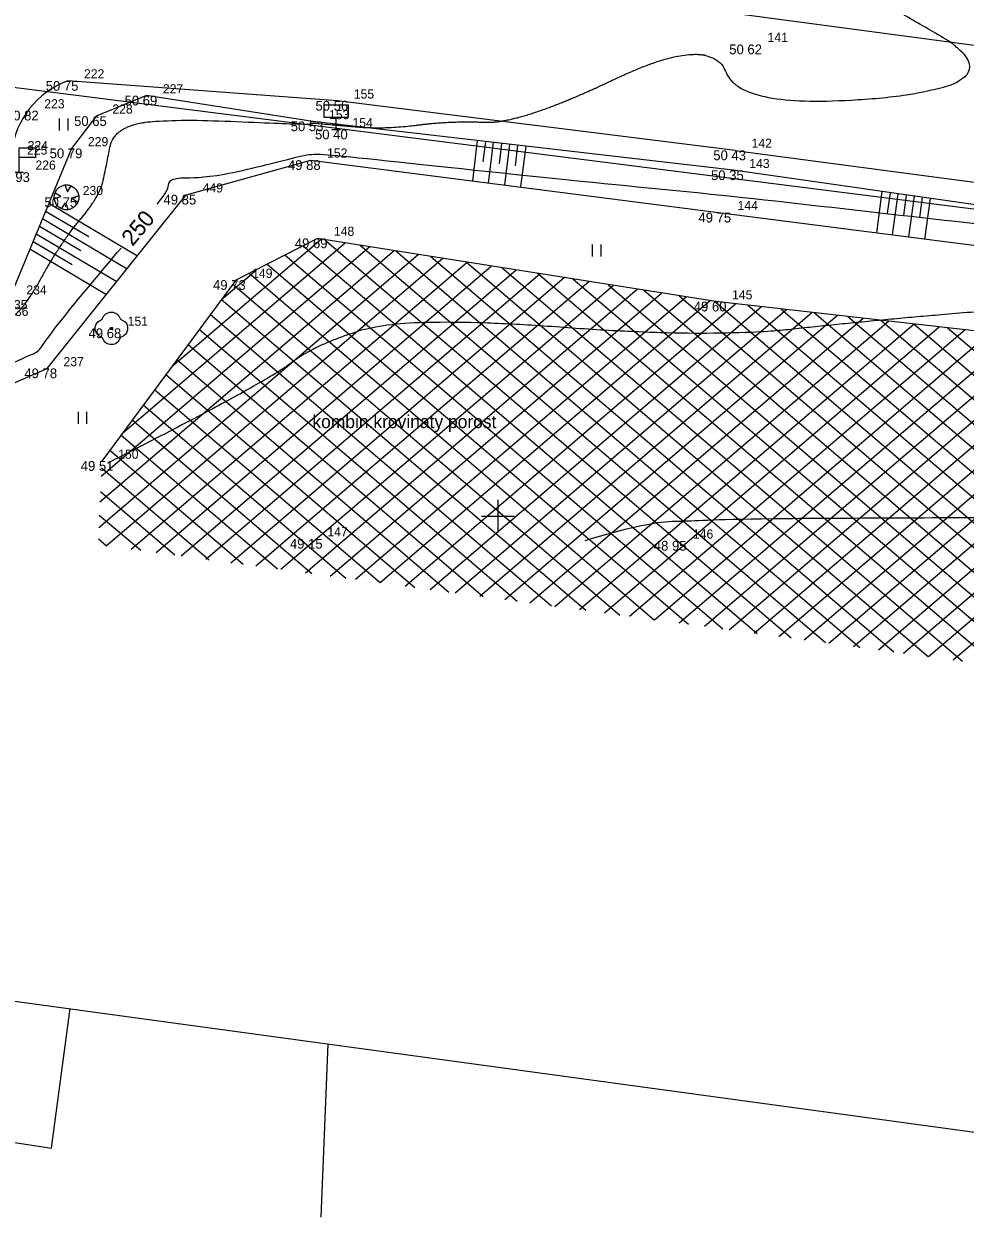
# Model space of a CAD drawing. Extents: x -704057 to -703795, y -1008732 to -1008584.
# Drawn here: x -703939.55 to -703910.66, y -1008696.51 to -1008659.9 of the extents above; entities that cross this region are included whole.
import ezdxf

# ---------------------------------------------------------------- set-up
doc = ezdxf.new("R2010")
doc.units = 0
for name, color, linetype in [('Z_body', 7, 'Continuous'), ('Z_body_cisla', 7, 'Continuous'), ('Z_body_vysky', 7, 'Continuous'), ('Z_dopravni_znaceni', 7, 'Continuous'), ('Z_hekt_sit', 7, 'Continuous'), ('Z_katastr_hranice', 7, 'Continuous'), ('Z_katastr_hranice_KU', 7, 'Continuous'), ('Z_katastr_vnitrni_kresba', 7, 'Continuous'), ('Z_komunikace_zpevn_pl', 7, 'Continuous'), ('Z_popis', 7, 'Continuous'), ('Z_teren_hrany_paty', 7, 'Continuous'), ('Z_vrstevnice_popis', 7, 'Continuous'), ('Z_vrstevnice_vedlejsi', 7, 'Continuous'), ('Z_zelen_jednotliva', 7, 'Continuous'), ('Z_zelen_souvisla', 7, 'Continuous')]:
    doc.layers.add(name, color=color, linetype=linetype)

# ---------------------------------------------------------------- blocks, each defined once
blk = doc.blocks.new('POINT_DISPLAY')
blk.add_line((0, 0), (0, 0))
blk = doc.blocks.new('Z24')
for p, q in [((-0.28, 0.28), (-0.23, 0.38)), ((-0.23, 0.38), (-0.17, 0.45)), ((-0.17, 0.45), (-0.05, 0.5)), ((-0.05, 0.5), (0.05, 0.5)), ((0.05, 0.5), (0.17, 0.45)), ((0.17, 0.45), (0.23, 0.38)), ((0.23, 0.38), (0.28, 0.28)), ((-0.5, 0.05), (-0.47, 0.13)), ((-0.5, -0.05), (-0.5, 0.05)), ((-0.47, 0.13), (-0.42, 0.2)), ((-0.42, 0.2), (-0.28, 0.28)), ((-0.03, -0.03), (-0.03, 0.03)), ((-0.03, 0.03), (0.03, 0.03)), ((0.03, 0.03), (0.03, -0.03)), ((0.28, 0.28), (0.42, 0.2)), ((0.42, 0.2), (0.47, 0.13)), ((0.47, 0.13), (0.5, 0.05)), ((0.5, 0.05), (0.5, -0.05)), ((-0.45, -0.17), (-0.5, -0.05)), ((-0.38, -0.23), (-0.45, -0.17)), ((-0.28, -0.28), (-0.38, -0.23)), ((-0.2, -0.42), (-0.28, -0.28)), ((0.03, -0.03), (-0.03, -0.03)), ((0.28, -0.28), (0.2, -0.42)), ((0.38, -0.23), (0.28, -0.28)), ((0.45, -0.17), (0.38, -0.23)), ((0.5, -0.05), (0.45, -0.17)), ((-0.13, -0.47), (-0.2, -0.42)), ((-0.05, -0.5), (-0.13, -0.47)), ((0.05, -0.5), (-0.05, -0.5)), ((0.13, -0.47), (0.05, -0.5)), ((0.2, -0.42), (0.13, -0.47))]:
    blk.add_line(p, q)
blk = doc.blocks.new('Z23')
for p, q in [((-0.13, 0.35), (-0.05, 0.38)), ((-0.05, 0.38), (0.05, 0.38)), ((-0.05, 0.38), (0.03, 0.17)), ((0.05, 0.38), (0.15, 0.35)), ((-0.38, 0.05), (-0.35, 0.13)), ((-0.38, -0.05), (-0.38, 0.05)), ((-0.38, -0.05), (-0.17, 0.03)), ((-0.35, 0.13), (-0.3, 0.23)), ((-0.17, 0.03), (-0.35, 0.13)), ((-0.3, 0.23), (-0.23, 0.3)), ((-0.23, 0.3), (-0.13, 0.35)), ((0.03, 0.17), (0.15, 0.35)), ((0.15, 0.35), (0.23, 0.3)), ((0.38, 0.05), (0.17, -0.03)), ((0.23, 0.3), (0.3, 0.23)), ((0.3, 0.23), (0.35, 0.15)), ((0.35, 0.15), (0.38, 0.05)), ((0.38, 0.05), (0.38, -0.05)), ((-0.35, -0.13), (-0.38, -0.05)), ((-0.3, -0.23), (-0.35, -0.13)), ((-0.23, -0.3), (-0.3, -0.23)), ((-0.15, -0.35), (-0.23, -0.3)), ((-0.15, -0.35), (-0.03, -0.17)), ((-0.05, -0.38), (-0.15, -0.35)), ((-0.03, -0.17), (0.05, -0.38)), ((0.15, -0.35), (0.05, -0.38)), ((0.23, -0.3), (0.15, -0.35)), ((0.17, -0.03), (0.35, -0.15)), ((0.3, -0.23), (0.23, -0.3)), ((0.35, -0.15), (0.3, -0.23)), ((0.38, -0.05), (0.35, -0.15)), ((0.05, -0.38), (-0.05, -0.38))]:
    blk.add_line(p, q)
blk = doc.blocks.new('Z524')
for p, q in [((0, 0), (0, 0.75)), ((0, 0.75), (0.5, 0.75)), ((0.5, 0.75), (0.5, 0.45)), ((0.5, 0.45), (0, 0.45)), ((-0.13, 0), (0.13, 0))]:
    blk.add_line(p, q)
blk = doc.blocks.new('Z526')
for p, q in [((0.38, 0.75), (-0.38, 0.75)), ((-0.38, 0.75), (-0.38, 0.38)), ((0.38, 0.38), (0.38, 0.75)), ((-0.38, 0.38), (0.38, 0.38)), ((0, 0), (0, 0.38)), ((-0.13, 0), (0.13, 0))]:
    blk.add_line(p, q)
blk = doc.blocks.new('Z306')
for p, q in [((-0.13, 0.17), (-0.13, -0.2)), ((0.13, 0.17), (0.13, -0.2))]:
    blk.add_line(p, q)

msp = doc.modelspace()

# ---------------------------------------------------------------- linework, layer by layer
at = {"layer": 'Z_hekt_sit'}
for p, q in [((-703925, -1008674.5), (-703925, -1008675.5)), ((-703925.5, -1008675), (-703924.5, -1008675))]:
    msp.add_line(p, q, dxfattribs=at)
at = {"layer": 'Z_katastr_hranice'}
for p, q in [((-703947.65, -1008660.85), (-703907.73, -1008665.91)), ((-703972.28, -1008685.45), (-703894.62, -1008696.05)), ((-703930.42, -1008696.51), (-703930.21, -1008691.19))]:
    msp.add_line(p, q, dxfattribs=at)
at = {"layer": 'Z_katastr_hranice_KU'}
msp.add_line((-703947.15, -1008655.63), (-703906.73, -1008661.04), dxfattribs=at)
at = {"layer": 'Z_katastr_vnitrni_kresba'}
for p, q in [((-703938.7, -1008694.39), (-703938.12, -1008690.11)), ((-703950.63, -1008692.56), (-703938.7, -1008694.39))]:
    msp.add_line(p, q, dxfattribs=at)
at = {"layer": 'Z_komunikace_zpevn_pl'}
for p, q in [((-703929.92, -1008662.26), (-703938.2, -1008661.65)), ((-703917.71, -1008663.78), (-703929.92, -1008662.26)), ((-703917.71, -1008663.78), (-703906.76, -1008665.24))]:
    msp.add_line(p, q, dxfattribs=at)
msp.add_arc((-703937.28, -1008664.15), 2.666, 110.1364, 173.2493, dxfattribs=at)
at = {"layer": 'Z_teren_hrany_paty'}
for p, q in [((-703935.78, -1008662.1), (-703937.33, -1008662.73)), ((-703930.68, -1008662.89), (-703935.78, -1008662.1)), ((-703937.33, -1008662.73), (-703938.08, -1008663.72)), ((-703917.78, -1008664.39), (-703930.68, -1008662.89)), ((-703925.63, -1008663.48), (-703925.78, -1008664.71)), ((-703925.38, -1008663.51), (-703925.46, -1008664.13)), ((-703925.14, -1008663.53), (-703925.29, -1008664.78)), ((-703924.89, -1008663.56), (-703924.96, -1008664.19)), ((-703924.64, -1008663.59), (-703924.79, -1008664.84)), ((-703938.08, -1008663.72), (-703939.97, -1008668.27)), ((-703924.39, -1008663.62), (-703924.47, -1008664.25)), ((-703924.14, -1008663.65), (-703924.3, -1008664.9)), ((-703934.56, -1008665.14), (-703930.74, -1008664.08)), ((-703930.74, -1008664.08), (-703918.14, -1008665.69)), ((-703907.01, -1008665.93), (-703917.78, -1008664.39)), ((-703913.21, -1008665.04), (-703913.38, -1008666.31)), ((-703938.83, -1008670.47), (-703934.56, -1008665.14)), ((-703938.78, -1008665.4), (-703936.06, -1008667.01)), ((-703912.96, -1008665.08), (-703913.05, -1008665.71)), ((-703912.72, -1008665.11), (-703912.89, -1008666.37)), ((-703912.47, -1008665.15), (-703912.55, -1008665.78)), ((-703912.22, -1008665.18), (-703912.39, -1008666.43)), ((-703911.97, -1008665.22), (-703912.06, -1008665.84)), ((-703911.73, -1008665.26), (-703911.9, -1008666.5)), ((-703938.88, -1008665.64), (-703937.55, -1008666.42)), ((-703918.14, -1008665.69), (-703907.01, -1008667.13)), ((-703939.07, -1008666.1), (-703937.8, -1008666.85)), ((-703938.97, -1008665.87), (-703936.38, -1008667.41)), ((-703939.17, -1008666.34), (-703936.69, -1008667.8)), ((-703939.36, -1008666.8), (-703937.01, -1008668.2)), ((-703939.26, -1008666.57), (-703938.06, -1008667.28)), ((-703940.68, -1008671.28), (-703938.83, -1008670.47))]:
    msp.add_line(p, q, dxfattribs=at)
at = {"layer": 'Z_vrstevnice_popis'}
for points in [[(-703935.451, -1008665.426), (-703935.149, -1008665.04), (-703935.119, -1008664.898), (-703935.079, -1008664.688), (-703934.778, -1008664.597), (-703933.704, -1008664.644), (-703930.729, -1008663.86), (-703930.56, -1008663.863), (-703922.686, -1008664.709), (-703917.99, -1008665.148), (-703912.22, -1008665.818), (-703907.01, -1008666.385), (-703897.89, -1008667.322), (-703895.624, -1008667.536), (-703894.683, -1008667.62), (-703889.646, -1008668.109), (-703886.88, -1008668.055), (-703885.948, -1008667.981), (-703882.942, -1008667.846), (-703876.005, -1008667.766), (-703871.926, -1008667.612), (-703869.247, -1008667.54), (-703868.688, -1008667.52)], [(-703943.199, -1008670.586), (-703942.532, -1008670.689), (-703942.405, -1008670.67), (-703940.763, -1008670.903), (-703940.641, -1008670.668), (-703939.322, -1008670.024), (-703939.083, -1008669.981), (-703938.742, -1008669.363), (-703937.122, -1008667.441), (-703936.564, -1008666.776)], [(-703922.315, -1008675.745), (-703920.255, -1008675.133), (-703919.418, -1008675.195), (-703918.102, -1008675.05), (-703907.476, -1008675.061), (-703903.573, -1008674.82), (-703895.854, -1008673.376), (-703883.381, -1008672.872), (-703883.154, -1008672.873), (-703883.026, -1008672.86), (-703882.713, -1008672.828), (-703878.528, -1008672.795), (-703877.019, -1008672.782)]]:
    msp.add_open_spline(points, degree=3, dxfattribs=at)
at = {"layer": 'Z_vrstevnice_vedlejsi'}
for points in [[(-703944.218, -1008669.537), (-703942.215, -1008669.847), (-703941.835, -1008669.79), (-703940.983, -1008669.911), (-703940.538, -1008669.059), (-703940.441, -1008669.011), (-703939.659, -1008668.87), (-703938.392, -1008666.573), (-703937.218, -1008665.198), (-703936.994, -1008664.158), (-703936.811, -1008663.182), (-703935.504, -1008662.788), (-703930.851, -1008662.989), (-703930.683, -1008662.945), (-703930.514, -1008662.948), (-703928.53, -1008663.14), (-703926.451, -1008662.869), (-703924.285, -1008662.962), (-703918.453, -1008660.188), (-703917.529, -1008662.583), (-703908.804, -1008661.73), (-703914.417, -1008658.58), (-703914.255, -1008657.775), (-703916.458, -1008657.408), (-703916.075, -1008656.975), (-703916.505, -1008656.883), (-703916.435, -1008655.703), (-703915.746, -1008656.007), (-703915.438, -1008656.225), (-703913.541, -1008656.36), (-703913.202, -1008656.502), (-703907.93, -1008657.256), (-703905.824, -1008657.417), (-703900.033, -1008658.024), (-703894.345, -1008658.848), (-703890.179, -1008659.57), (-703887.702, -1008659.871), (-703882.266, -1008660.175), (-703878.347, -1008660.959), (-703873.149, -1008661.531), (-703869.803, -1008661.293), (-703867.148, -1008661.514), (-703856.66, -1008662.48), (-703848.555, -1008661.935), (-703843.582, -1008661.747), (-703840.018, -1008661.713), (-703835.656, -1008661.182), (-703832.168, -1008661.259), (-703831.497, -1008661.293), (-703819.488, -1008662.346), (-703817.521, -1008662.543), (-703807.841, -1008663.114), (-703805.78, -1008663.132)], [(-703806.645, -1008669.413), (-703810.064, -1008669.091), (-703818.896, -1008668.231), (-703821.949, -1008667.886), (-703832.348, -1008666.911), (-703832.429, -1008666.905), (-703837.82, -1008666.255), (-703832.713, -1008666.908), (-703832.355, -1008666.952), (-703825.705, -1008667.99), (-703819.056, -1008669.026), (-703815.993, -1008669.415), (-703810.462, -1008670.24), (-703806.87, -1008671.09), (-703808.766, -1008673.591), (-703809.75, -1008673.886), (-703817.454, -1008673.52), (-703819.628, -1008673.248), (-703826.836, -1008673.24), (-703833.27, -1008673.353), (-703835.286, -1008673.278), (-703844.44, -1008672.81), (-703850.152, -1008672.821), (-703855.806, -1008672.275), (-703857.13, -1008672.165), (-703860.162, -1008671.947), (-703871.237, -1008671.005), (-703876.973, -1008670.473), (-703883.276, -1008669.953), (-703888.652, -1008669.207), (-703892.007, -1008668.787), (-703895.701, -1008668.459), (-703900.931, -1008667.965), (-703907.22, -1008668.487), (-703913.351, -1008668.979), (-703918.495, -1008669.549), (-703927.701, -1008668.863), (-703930.6, -1008669.724), (-703932.124, -1008670.909), (-703936.972, -1008673.376)]]:
    msp.add_open_spline(points, degree=2, dxfattribs=at)
at = {"layer": 'Z_zelen_souvisla'}
for p, q in [((-703935, -1008670.41), (-703930.42, -1008666.5)), ((-703930.53, -1008666.48), (-703933.04, -1008667.76)), ((-703918.31, -1008668.42), (-703930.53, -1008666.48)), ((-703930.31, -1008666.52), (-703915.99, -1008678.74)), ((-703937.21, -1008674.56), (-703928.18, -1008666.85)), ((-703937.17, -1008673.77), (-703928.93, -1008666.73)), ((-703936.52, -1008672.46), (-703929.68, -1008666.62)), ((-703930.97, -1008666.71), (-703917.04, -1008678.6)), ((-703929.22, -1008666.69), (-703914.94, -1008678.88)), ((-703928.13, -1008666.86), (-703913.89, -1008679.03)), ((-703937.25, -1008675.35), (-703927.44, -1008666.97)), ((-703937.02, -1008675.91), (-703926.69, -1008667.09)), ((-703936.25, -1008676.01), (-703925.94, -1008667.21)), ((-703931.53, -1008666.99), (-703918.09, -1008678.46)), ((-703927.05, -1008667.03), (-703912.84, -1008679.17)), ((-703925.96, -1008667.21), (-703911.79, -1008679.31)), ((-703935.49, -1008676.12), (-703925.2, -1008667.33)), ((-703934.72, -1008676.22), (-703924.45, -1008667.45)), ((-703933.96, -1008676.32), (-703923.7, -1008667.56)), ((-703933.48, -1008668.35), (-703932.41, -1008667.44)), ((-703932.63, -1008667.55), (-703920.2, -1008678.18)), ((-703932.08, -1008667.27), (-703919.15, -1008678.32)), ((-703924.87, -1008667.38), (-703910.74, -1008679.45)), ((-703923.78, -1008667.55), (-703909.68, -1008679.59)), ((-703933.04, -1008667.76), (-703937.15, -1008673.31)), ((-703933.19, -1008676.43), (-703922.96, -1008667.68)), ((-703933.13, -1008667.88), (-703921.25, -1008678.04)), ((-703932.43, -1008676.53), (-703922.21, -1008667.8)), ((-703931.66, -1008676.63), (-703921.46, -1008667.92)), ((-703922.7, -1008667.72), (-703908.63, -1008679.73)), ((-703921.61, -1008667.9), (-703907.58, -1008679.88)), ((-703933.48, -1008668.35), (-703922.3, -1008677.89)), ((-703930.9, -1008676.74), (-703920.72, -1008668.04)), ((-703930.14, -1008676.84), (-703919.97, -1008668.16)), ((-703929.37, -1008676.94), (-703919.22, -1008668.27)), ((-703920.52, -1008668.07), (-703906.53, -1008680.02)), ((-703919.43, -1008668.24), (-703905.48, -1008680.16)), ((-703928.61, -1008677.04), (-703918.48, -1008668.39)), ((-703927.84, -1008677.15), (-703917.7, -1008668.49)), ((-703927.08, -1008677.25), (-703916.92, -1008668.58)), ((-703926.31, -1008677.35), (-703916.14, -1008668.66)), ((-703918.35, -1008668.41), (-703904.43, -1008680.3)), ((-703907.4, -1008669.65), (-703918.31, -1008668.42)), ((-703917.32, -1008668.53), (-703903.38, -1008680.44)), ((-703916.3, -1008668.65), (-703902.33, -1008680.58)), ((-703933.82, -1008668.81), (-703923.35, -1008677.75)), ((-703925.55, -1008677.46), (-703915.36, -1008668.75)), ((-703924.78, -1008677.56), (-703914.57, -1008668.84)), ((-703924.02, -1008677.66), (-703913.79, -1008668.93)), ((-703923.25, -1008677.77), (-703913.01, -1008669.02)), ((-703915.28, -1008668.76), (-703901.28, -1008680.73)), ((-703914.26, -1008668.88), (-703900.22, -1008680.87)), ((-703913.24, -1008668.99), (-703899.17, -1008681.01)), ((-703934.16, -1008669.27), (-703924.4, -1008677.61)), ((-703922.49, -1008677.87), (-703912.23, -1008669.11)), ((-703921.72, -1008677.97), (-703911.45, -1008669.19)), ((-703920.96, -1008678.07), (-703910.66, -1008669.28)), ((-703920.19, -1008678.18), (-703909.88, -1008669.37)), ((-703919.43, -1008678.28), (-703909.1, -1008669.46)), ((-703912.22, -1008669.11), (-703898.12, -1008681.15)), ((-703911.2, -1008669.22), (-703897.07, -1008681.29)), ((-703934.5, -1008669.74), (-703925.45, -1008677.47)), ((-703918.66, -1008678.38), (-703908.32, -1008669.55)), ((-703917.9, -1008678.49), (-703907.54, -1008669.63)), ((-703917.13, -1008678.59), (-703906.75, -1008669.72)), ((-703916.37, -1008678.69), (-703905.96, -1008669.81)), ((-703915.6, -1008678.8), (-703905.18, -1008669.89)), ((-703914.84, -1008678.9), (-703904.39, -1008669.98)), ((-703914.08, -1008679), (-703903.61, -1008670.06)), ((-703913.31, -1008679.1), (-703902.82, -1008670.15)), ((-703934.85, -1008670.2), (-703926.5, -1008677.33)), ((-703912.55, -1008679.21), (-703902.04, -1008670.23)), ((-703911.78, -1008679.31), (-703901.25, -1008670.32)), ((-703911.02, -1008679.41), (-703900.47, -1008670.4)), ((-703935.19, -1008670.66), (-703927.55, -1008677.19)), ((-703935.53, -1008671.13), (-703928.61, -1008677.04)), ((-703935.88, -1008671.59), (-703929.66, -1008676.9)), ((-703936.22, -1008672.05), (-703930.71, -1008676.76)), ((-703936.56, -1008672.52), (-703931.76, -1008676.62)), ((-703936.91, -1008672.98), (-703932.81, -1008676.48)), ((-703937.16, -1008673.52), (-703933.86, -1008676.34)), ((-703937.19, -1008674.25), (-703934.91, -1008676.19)), ((-703937.23, -1008674.97), (-703935.96, -1008676.05)), ((-703937.26, -1008675.7), (-703937.01, -1008675.91))]:
    msp.add_line(p, q, dxfattribs=at)

# ---------------------------------------------------------------- block references
at = {"layer": 'Z_body'}
for p in [(-703917.22, -1008660.53), (-703938.2, -1008661.65), (-703935.78, -1008662.1), (-703929.92, -1008662.26), (-703939.42, -1008662.56), (-703937.33, -1008662.73), (-703930.68, -1008662.89), (-703929.96, -1008663.14), (-703938.08, -1008663.72), (-703917.71, -1008663.78), (-703930.74, -1008664.08), (-703917.78, -1008664.39), (-703938.24, -1008665.22), (-703934.56, -1008665.14), (-703918.14, -1008665.69), (-703930.53, -1008666.48), (-703933.04, -1008667.76), (-703918.31, -1008668.42), (-703936.86, -1008669.24), (-703938.83, -1008670.47), (-703937.15, -1008673.31), (-703930.73, -1008675.7), (-703919.51, -1008675.76)]:
    msp.add_blockref('POINT_DISPLAY', p, dxfattribs=at)
at = {"layer": 'Z_dopravni_znaceni'}
for name, p in [('Z526', (-703929.96, -1008663.14)), ('Z524', (-703939.69, -1008664.45))]:
    msp.add_blockref(name, p, dxfattribs=at)
at = {"layer": 'Z_popis'}
for p in [(-703938.33, -1008662.97), (-703921.97, -1008666.84), (-703937.75, -1008671.97)]:
    msp.add_blockref('Z306', p, dxfattribs=at)
at = {"layer": 'Z_zelen_jednotliva'}
for name, p in [('Z23', (-703938.24, -1008665.22)), ('Z24', (-703936.86, -1008669.24))]:
    msp.add_blockref(name, p, dxfattribs=at)

# ---------------------------------------------------------------- texts
at = {"layer": 'Z_body_cisla'}
for s, p in [('141', (-703916.72, -1008660.45)), ('222', (-703937.7, -1008661.57)), ('227', (-703935.28, -1008662.03)), ('155', (-703929.42, -1008662.19)), ('223', (-703938.92, -1008662.49)), ('228', (-703936.83, -1008662.65)), ('153', (-703930.18, -1008662.82)), ('154', (-703929.46, -1008663.07)), ('224', (-703939.43, -1008663.77)), ('229', (-703937.58, -1008663.65)), ('142', (-703917.21, -1008663.7)), ('225', (-703939.45, -1008663.91)), ('152', (-703930.24, -1008664)), ('226', (-703939.19, -1008664.37)), ('143', (-703917.28, -1008664.32)), ('230', (-703937.74, -1008665.15)), ('449', (-703934.06, -1008665.07)), ('144', (-703917.64, -1008665.61)), ('148', (-703930.03, -1008666.4)), ('149', (-703932.54, -1008667.69)), ('234', (-703939.47, -1008668.2)), ('145', (-703917.81, -1008668.35)), ('235', (-703940.06, -1008668.65)), ('236', (-703940.03, -1008668.86)), ('151', (-703936.36, -1008669.16)), ('237', (-703938.33, -1008670.4)), ('150', (-703936.65, -1008673.24)), ('147', (-703930.23, -1008675.62)), ('146', (-703919.01, -1008675.69))]:
    msp.add_text(s, height=0.28, dxfattribs=at).set_placement(p)
at = {"layer": 'Z_body_vysky'}
for s, p in [('50 62', (-703917.895, -1008660.83)), ('50 75', (-703938.875, -1008661.95)), ('50 69', (-703936.455, -1008662.4)), ('50 56', (-703930.595, -1008662.56)), ('50 82', (-703940.095, -1008662.86)), ('50 65', (-703938.005, -1008663.03)), ('50 53', (-703931.355, -1008663.19)), ('50 40', (-703930.61, -1008663.44)), ('50 79', (-703938.755, -1008664.02)), ('50 43', (-703918.385, -1008664.08)), ('49 88', (-703931.44, -1008664.38)), ('50 93', (-703940.365, -1008664.75)), ('50 35', (-703918.455, -1008664.69)), ('50 75', (-703938.915, -1008665.52)), ('49 85', (-703935.26, -1008665.44)), ('49 75', (-703918.84, -1008665.99)), ('49 69', (-703931.23, -1008666.78)), ('49 73', (-703933.74, -1008668.06)), ('49 60', (-703918.985, -1008668.72)), ('49 68', (-703937.56, -1008669.54)), ('49 78', (-703939.53, -1008670.77)), ('49 51', (-703937.8, -1008673.61)), ('49 15', (-703931.38, -1008676)), ('48 95', (-703920.21, -1008676.06))]:
    msp.add_text(s, height=0.3, dxfattribs=at).set_placement(p)
at = {"layer": 'Z_popis'}
msp.add_text('kombin.krovinaty porost', height=0.4, dxfattribs=at).set_placement((-703930.69, -1008672.3))
at = {"layer": 'Z_vrstevnice_popis'}
msp.add_text('250', height=0.5, rotation=50.2799, dxfattribs=at).set_placement((-703936.21, -1008666.745))

doc.saveas('drawing.dxf')
